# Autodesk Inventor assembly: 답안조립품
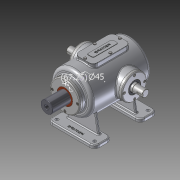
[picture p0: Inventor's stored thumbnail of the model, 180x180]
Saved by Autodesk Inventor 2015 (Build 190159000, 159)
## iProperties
Created: 2016-02
Part Number: 답안조립품
Document SubType Name: Assembly
Designer: Administrator
Mass: 8191.33 g
Surface Area: 4241.86 cm^2
Volume: 1855.51 cm^3
Density: 4.41461 g/cm^3
Author: Administrator
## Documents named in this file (15)
- C:\Users\Administrator\Desktop\360220V1012\답안조립품.iam
- C:\Users\Administrator\Desktop\360220V1012\본체.ipt
- C:\Users\Administrator\Desktop\360220V1012\슬라이드 커버.ipt
- C:\Users\Administrator\Desktop\360220V1012\볼트 M4x0.7.ipt
- C:\Users\Administrator\Desktop\360220V1012\축 커버.ipt
- C:\Users\Administrator\Desktop\360220V1012\오일실.ipt
- 오일실.ipt
- C:\Users\Administrator\Desktop\360220V1012\베어링 6205.ipt
- 베어링 6205.ipt
- C:\Users\Administrator\Desktop\360220V1012\상부커버.ipt
- C:\Users\Administrator\Desktop\360220V1012\육각머리볼트 M4.ipt
- C:\Users\Administrator\Desktop\360220V1012\부시.ipt
- C:\Users\Administrator\Desktop\360220V1012\편심축.ipt
- C:\Users\Administrator\Desktop\360220V1012\가변스프링.ipt
- C:\Users\Administrator\Desktop\360220V1012\슬라이드.ipt
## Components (13 placed, 2 different names)
1. 가변스프링:1
2. M4x0.7:1
3. M4x0.7:2
4. M4x0.7:3
5. M4x0.7:4
6. M4x0.7:5
7. M4x0.7:7
8. M4x0.7:8
9. M4x0.7:9
10. M4x0.7:6
11. M4x0.7:10
12. M4x0.7:11
13. M4x0.7:12
